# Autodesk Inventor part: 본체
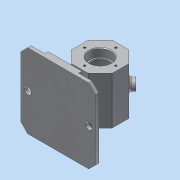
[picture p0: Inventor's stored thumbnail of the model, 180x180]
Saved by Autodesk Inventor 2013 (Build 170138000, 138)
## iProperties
Created: 2018-06
Part Number: 본체
Material: 알루미늄 6061
Document SubType Name: Modeling
Designer: Administrator
Density: 2.71 g/cm^3
Mass: 554.043 g
Surface Area: 601.935 cm^2
Volume: 204.444 cm^3
Author: Administrator
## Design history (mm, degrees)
sketch "스케치1" dims "d0" = 60
  geometry: L1 (30, 12.426)-(30, -12.426); L2 (30, -12.426)-(12.426, -30); L3 (12.426, -30)-(-12.426, -30); L4 (-12.426, -30)-(-30, -12.426); L5 (-30, -12.426)-(-30, 12.426); L6 (-30, 12.426)-(-12.426, 30); L7 (-12.426, 30)-(12.426, 30); L8 (12.426, 30)-(30, 12.426); L9 (55, -57)-(55, -62); L10 (55, -62)-(-55, -62); L11 (-55, -62)-(-55, -57); L12 (-25, -52)-(25, -52); L13 (25, -52)-(25, -57); L14 (-25, -57)-(-25, -52); L15 (-55, -57)-(25, -57); L16 (25, -57)-(55, -57); 7 further points
  constraints: 32 end point, 4 midpoint, 4 parallel, 3 horizontal, 3 perpendicular, 3 vertical alignment, 2 coincident, 1 collinear, 1 point on line, 20 other
  dimensions: "d3" = 5 distance of L10.end L11.end; "d4" = 10 distance between parallel lines of L10 L12; "d5" = 110 distance of L9.end L10.end; "d6" = 62 distance from line of point (0, 0) L10; "d7" = 50 distance of L12.start L12.end
extrude "돌출1" new body sketch "스케치1" distance "d1" = 35; taper "d2" = 0 deg
extrude "돌출2" join sketch "스케치1" distance "d8" = 55; taper "d9" = 0 deg
extrude "돌출3" join sketch "스케치1" distance "d10" = 55; taper "d11" = 0 deg
chamfer "모따기1" distance "d13" = 10; stored, may be unused: second distance "d14" = 2, angle "d15" = 45 deg
sketch "스케치2"
  geometry: 2 further points
  constraints: 1 coincident
hole "구멍1" sketch "스케치2" at (0, 0) diameter "d18" = 28; stored, may be unused: countersink angle "d22" = 90 deg, drill point angle "d24" = 0 deg; dims "d19" = 6, "d20" = 32, "d21" = 12, "d23" = 15
sketch "스케치4"
  geometry: C1 r 25 at (0, 0); 1 further point
  constraints: 1 centre point, 1 coincident
  dimensions: "d40" = 50 diameter of C1
extrude "돌출4" cut sketch "스케치4" distance "d41" = 20; taper "d42" = 0 deg
sketch "스케치3"
  geometry: C1 r 16 at (0, 0) reference; 1 further point
  constraints: 1 vertical alignment
  dimensions: "d25" = 23 distance of C1.centre point (0, 23)
hole "구멍2" sketch "스케치3" at (0, 23) diameter "d26" = 3.242; stored, may be unused: countersink angle "d30" = 90 deg, drill point angle "d32" = 118 deg; dims "d27" = 8, "d28" = 32, "d29" = 12, "d31" = 10
chamfer "모따기2" distance "d36" = 1; stored, may be unused: second distance "d37" = 2, angle "d38" = 45 deg
fillet "모깎기2" dims "d39" = 0.3, "d43" = 3
sketch "스케치5"
  geometry: L1 (25, 31)-(25, 31); L2 (30, 36)-(30, 74); L3 (25, 79)-(25, 79); L4 (20, 74)-(20, 36); A1 r 5 centre (25, 74) between (25, 79) and (20, 74); A2 r 5 centre (25, 74) between (30, 74) and (25, 79); A3 r 5 centre (25, 36) between (20, 36) and (25, 31); A4 r 5 centre (25, 36) between (25, 31) and (30, 36); 6 further points
  constraints: 8 end point, 8 point on circle, 8 tangent, 6 point on line, 4 centre point, 3 equal radius, 2 midpoint, 2 parallel, 1 horizontal, 1 horizontal alignment, 1 perpendicular, 1 vertical alignment
  dimensions: "d44" = 48 distance of point (20, 79) point (20, 31); "d46" = 10 distance of point (30, 79) point (20, 79); "d47" = 5 radius of A1
extrude "돌출5" join sketch "스케치5" stored distance "d48" = 20; taper "d49" = 0 deg
fillet "모깎기3" dims "d50" = 2
sketch "스케치6"
  geometry: L1 (30, 100)-(30, 10) reference; C1 r 5 at (20, 55); 1 further point
  constraints: 1 centre point, 1 horizontal alignment
  dimensions: "d51" = 10 diameter of C1; "d52" = 10 distance from line of L1 C1.centre
extrude "돌출6" cut sketch "스케치6" stored distance "d53" = 20; taper "d54" = 0 deg
fillet "모깎기4" dims "d55" = 1
sketch "스케치7"
  geometry: C1 r 8 at (12.012, 35); 1 further point
  constraints: 1 centre point, 1 coincident
  dimensions: "d56" = 16 diameter of C1
extrude "돌출7" join sketch "스케치7" distance "d57" = 7; taper "d58" = 0 deg
hole "구멍3" diameter "d61" = 8; stored, may be unused: countersink angle "d65" = 90 deg, drill point angle "d67" = 0 deg; dims "d59" = 10, "d60" = 10, "d62" = 8, "d63" = 32, "d64" = 12, "d66" = 10
fillet "모깎기5" dims "d68" = 3
chamfer "모따기3" distance "d69" = 1; stored, may be unused: second distance "d70" = 2, angle "d71" = 45 deg
sketch "스케치8"
  geometry: L1 (24.024, -70)-(0, -70) reference; L2 (-17.988, 0)-(-17.988, -70) reference; 2 further points
  constraints: 1 other
  dimensions: "d72" = 35 distance from line of point (12.012, -35) L1; "d73" = 30 distance from line of point (12.012, -35) L2
feature "엠보싱1" sketch "스케치8" dims "d74" = 0.5, "d75" = 0
node "솔리드1"
pattern_circular "원형 패턴1" dims angle "d34" = 360 deg
mirror "대칭1"
mirror "대칭2"
